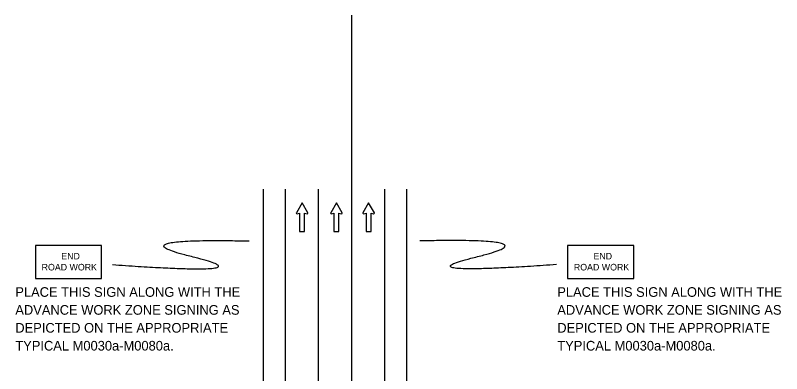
# Model space of a CAD drawing. Extents: x 16741 to 18475, y 7000 to 8315.
# Drawn here: x 16771 to 17328, y 8055 to 8315 of the extents above; entities that cross this region are included whole.
import ezdxf

# ---------------------------------------------------------------- set-up
doc = ezdxf.new("R2010")
doc.units = 0
for name, color, linetype in [('ALI_LEGAL_EX', 7, 'Continuous'), ('MT_SCRATCH_LEVEL_E', 7, 'Continuous'), ('PAVT_EDGE_EX', 7, 'Continuous'), ('TRAFFIC_SIGNS_PR', 7, 'Continuous')]:
    doc.layers.add(name, color=color, linetype=linetype)

msp = doc.modelspace()

# ---------------------------------------------------------------- linework, layer by layer
at = {"layer": 'ALI_LEGAL_EX'}
for p, q in [((16991.15, 8188.6), (16991.15, 7369.05)), ((17015.15, 8188.6), (17015.15, 7369.05))]:
    msp.add_line(p, q, dxfattribs=at)
for points in [[(16991.15, 8188.6), (16991.15, 8163.6)], [(17015.15, 8188.6), (17015.15, 8163.6)], [(16991.15, 8088.6), (16991.15, 8063.6)], [(17015.15, 8088.6), (17015.15, 8063.6)]]:
    msp.add_lwpolyline(points, dxfattribs=at)
at = {"layer": 'MT_SCRATCH_LEVEL_E'}
for p, q in [((16979.32, 8178.76), (16975.21, 8171.51)), ((16983.46, 8171.51), (16979.32, 8178.76)), ((17004.27, 8178.76), (17000.16, 8171.51)), ((17008.42, 8171.51), (17004.27, 8178.76)), ((17027.68, 8178.76), (17023.57, 8171.51)), ((17031.83, 8171.51), (17027.68, 8178.76)), ((16975.69, 8170.83), (16977.46, 8171.15)), ((16977.46, 8171.15), (16977.46, 8157.89)), ((16981.21, 8157.89), (16981.21, 8171.15)), ((16981.21, 8171.15), (16982.98, 8170.83)), ((17000.64, 8170.83), (17002.42, 8171.15)), ((17002.42, 8171.15), (17002.42, 8157.89)), ((17006.16, 8157.89), (17006.16, 8171.15)), ((17006.16, 8171.15), (17007.94, 8170.83)), ((17024.05, 8170.83), (17025.83, 8171.15)), ((17025.83, 8171.15), (17025.83, 8157.89)), ((17029.57, 8157.89), (17029.57, 8171.15)), ((17029.57, 8171.15), (17031.35, 8170.83)), ((16977.46, 8157.89), (16981.21, 8157.89)), ((17002.42, 8157.89), (17006.16, 8157.89)), ((17025.83, 8157.89), (17029.57, 8157.89))]:
    msp.add_line(p, q, dxfattribs=at)
for centre, start, end in [((16975.61, 8171.29), 150.4248, 279.9638), ((16983.05, 8171.29), 260.0362, 29.7731), ((17000.56, 8171.29), 150.4248, 279.9638), ((17008.01, 8171.29), 260.0362, 29.7731), ((17023.98, 8171.29), 150.4248, 279.9638), ((17031.42, 8171.29), 260.0362, 29.7731)]:
    msp.add_arc(centre, 0.463, start, end, dxfattribs=at)
at = {"layer": 'PAVT_EDGE_EX'}
for p, q in [((17015.15, 8314.85), (17015.15, 7485.67)), ((16951.15, 8188.6), (16951.15, 7369.05)), ((16967.15, 8188.6), (16967.15, 7369.05)), ((17039.15, 8188.6), (17039.15, 7369.05)), ((17055.15, 8188.6), (17055.15, 7369.05))]:
    msp.add_line(p, q, dxfattribs=at)
at = {"layer": 'TRAFFIC_SIGNS_PR'}
for points in [[(16785.75, 8123.69), (16833.75, 8123.69), (16833.75, 8147.69), (16785.75, 8147.69)], [(17172.17, 8123.69), (17220.17, 8123.69), (17220.17, 8147.69), (17172.17, 8147.69)]]:
    msp.add_lwpolyline(points, close=True, dxfattribs=at)
for points in [[(16841.61, 8133.87), (16956.84, 8125.64), (16842.93, 8153.22), (16940.87, 8151.05)], [(17164.1, 8133.87), (17048.88, 8125.64), (17162.79, 8153.22), (17064.84, 8151.05)]]:
    msp.add_open_spline(points, degree=2, dxfattribs=at)

# ---------------------------------------------------------------- texts
for s, height, p in [('END', 4.789, (16804.5, 8137.61)), ('END', 4.789, (17190.92, 8137.61)), ('ROAD WORK', 4.789, (16790.26, 8129.62)), ('ROAD WORK', 4.789, (17176.68, 8129.62)), ('PLACE THIS SIGN ALONG WITH THE', 7, (16771.16, 8110.47)), ('PLACE THIS SIGN ALONG WITH THE', 7, (17164.65, 8110.47)), ('ADVANCE WORK ZONE SIGNING AS', 7, (16771.16, 8097.47)), ('ADVANCE WORK ZONE SIGNING AS', 7, (17164.65, 8097.47)), ('DEPICTED ON THE APPROPRIATE', 7, (16771.16, 8084.47)), ('DEPICTED ON THE APPROPRIATE', 7, (17164.65, 8084.47)), ('TYPICAL M0030a-M0080a.', 7, (16771.16, 8071.47)), ('TYPICAL M0030a-M0080a.', 7, (17164.65, 8071.47))]:
    msp.add_text(s, height=height, dxfattribs=at).set_placement(p)

doc.saveas('drawing.dxf')
